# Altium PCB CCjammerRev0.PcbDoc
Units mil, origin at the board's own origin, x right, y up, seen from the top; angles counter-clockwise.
Board outline 3150 x 2000 mil, 2 copper layers (Top Layer, Bottom Layer); 11 components, 6 nets, 28 pads, 2 vias.
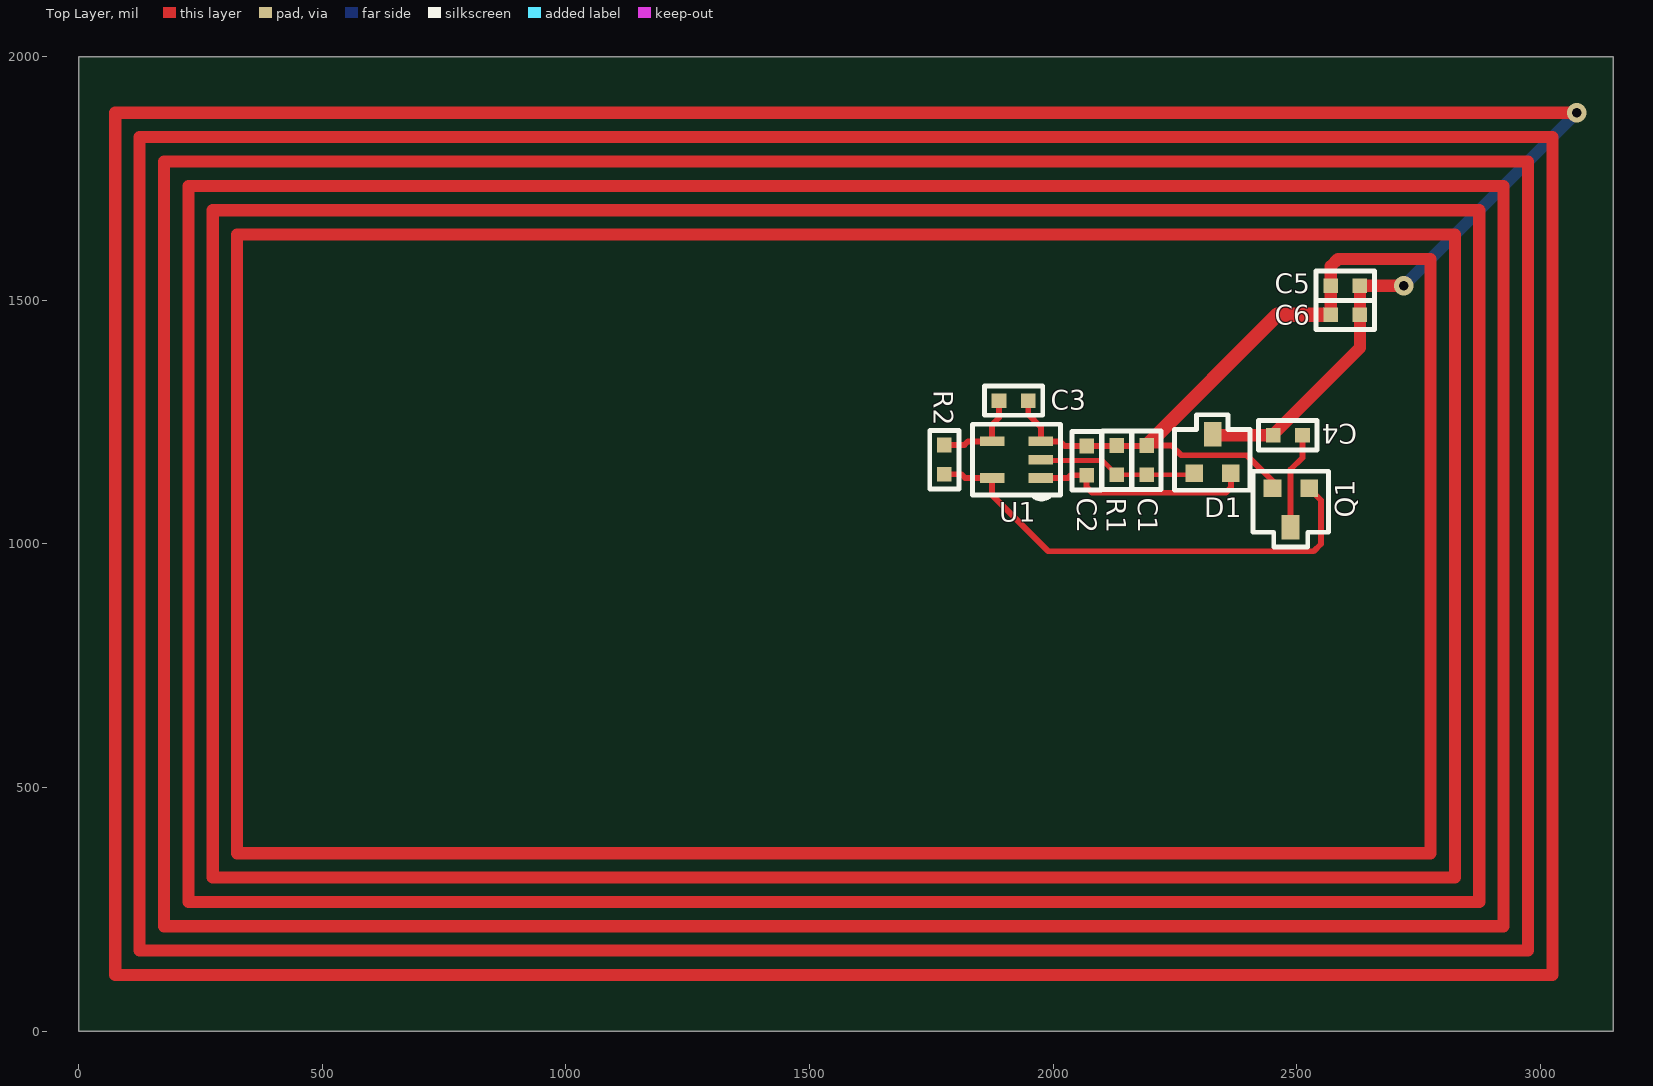
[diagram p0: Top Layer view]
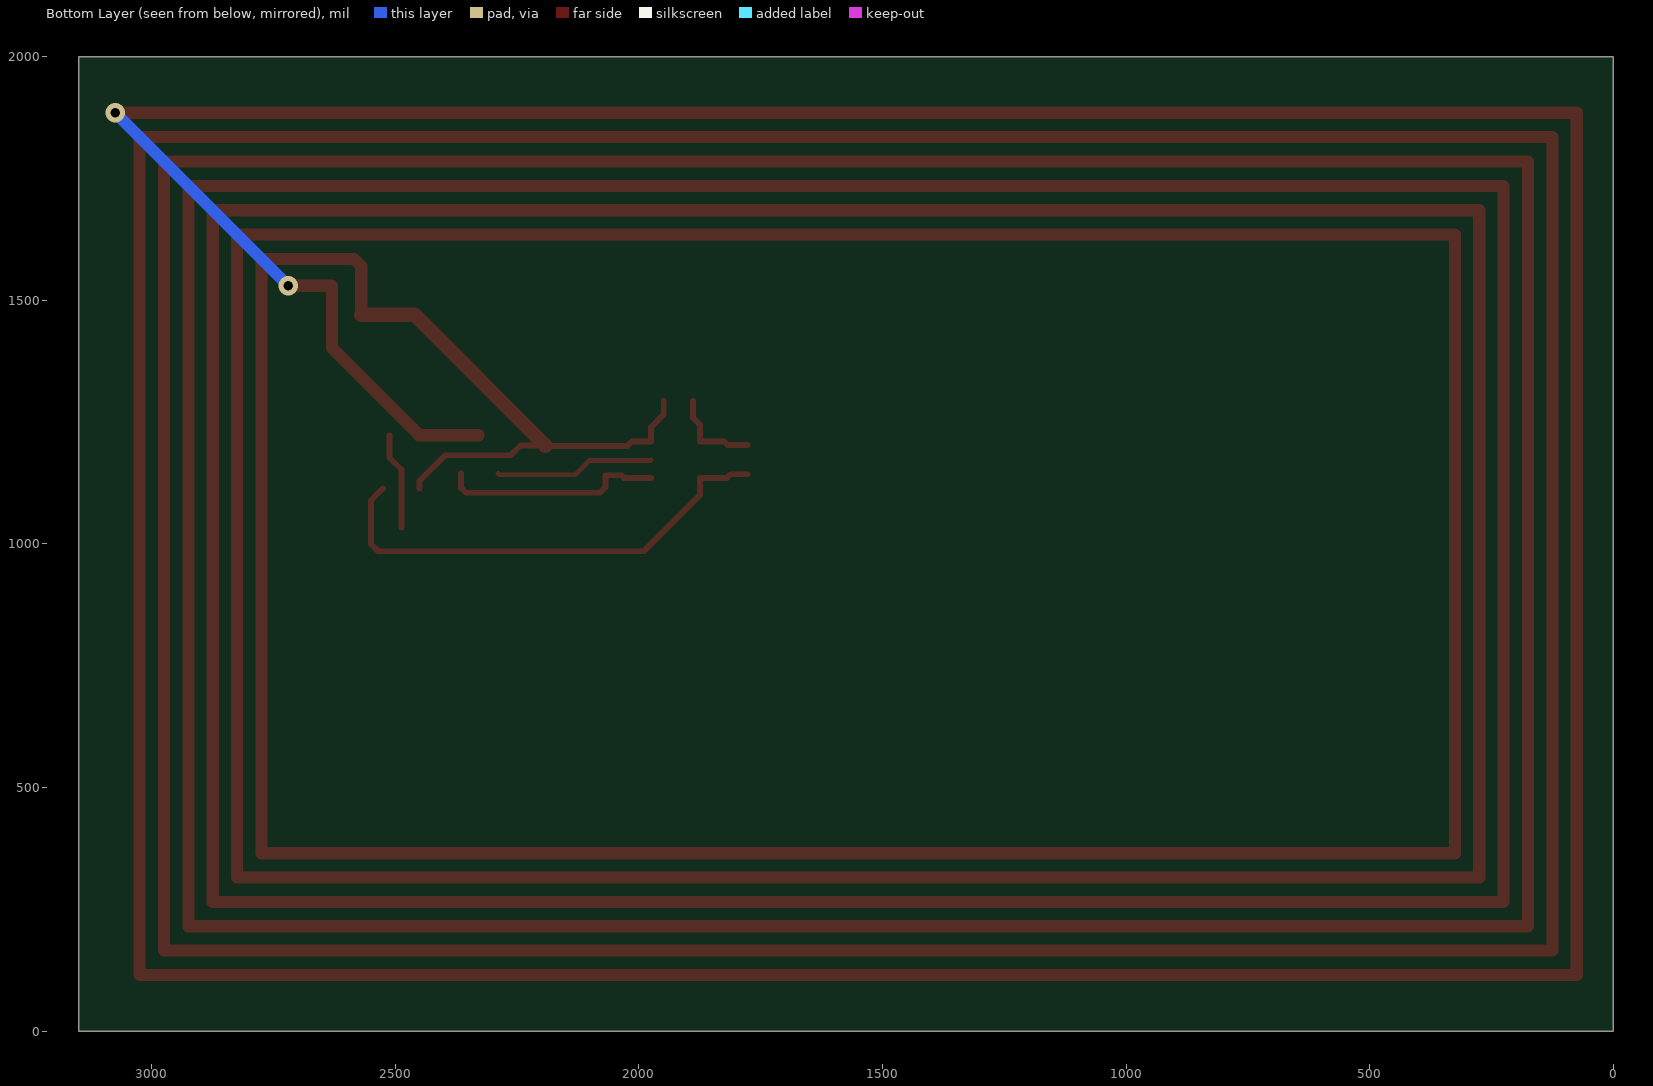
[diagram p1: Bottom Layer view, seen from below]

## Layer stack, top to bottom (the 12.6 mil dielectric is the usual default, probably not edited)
Top Layer: signal copper 1.4
Dielectric: dielectric 12.6, FR-4, Dk 4.8
Bottom Layer: signal copper 1.4

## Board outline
0,0 0,2000 3150,2000 3150,0

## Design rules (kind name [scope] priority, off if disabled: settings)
Clearance [All] p1: gap=10
PolygonConnect [All] p1: connectstyle=Relief reliefconductorwidth=10 reliefentries=4 polygonreliefangle="90 Angle"
RoutingVias [All] p1: holewidth=28 width=50 viastyle="Through Hole" minholewidth=28 minwidth=50 maxholewidth=28 maxwidth=50
SilkscreenOverComponentPads [All] p1: minsilkscreentomaskgap=10
SolderMaskExpansion [All] p1: expansion=4
Width [All] p1: maxlimit=100 minlimit=6 preferedwidth=10
27 further rules are at their usual default settings.

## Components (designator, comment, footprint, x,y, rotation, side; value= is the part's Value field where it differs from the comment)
C1 "270pf" 0603_072205 2192,1172 r270 top
C2 "0.1uf" 0603_072205 2069,1171 r270 top
C3 "10uf" 0603_072205 1919,1294 r180 top
C4 "10pf" 0603_072205 2482,1223 r180 top
C5 "10pf" 0603_072205 2600,1530 r0 top
C6 "10pf" 0603_072205 2600,1470 r0 top
D1 "BAT721A" SOT23_012105 2327,1185 r0 top
Q1 "VN0605" "SOT23 FET_012005" 2488,1074 r180 top
R1 "500K" 0603_072205 2131,1172 r270 top
R2 "46K" 0603_072205 1777,1173 r270 top
U1 "MIC1555" SOT25_030205 1925,1173 r0 top

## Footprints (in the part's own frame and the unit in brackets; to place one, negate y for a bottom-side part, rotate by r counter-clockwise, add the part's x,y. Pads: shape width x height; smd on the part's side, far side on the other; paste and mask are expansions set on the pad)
0603_072205 [mil] "SM"
  rect 30x30 smd: 1(-30,0) 2(30,0)
  silkscreen extent -60,-30 60,30
"SOT23 FET_012005" [mil] "SMT"
  rect 36x50 smd: D(0.5,40)
  rect 36x36 smd: G(-37.5,-40) S(37.5,-40)
  silkscreen extent -78,-75 78,80
SOT23_012105 [mil] "SMT"
  rect 36x36 smd: 1(-37.5,-40) 2(37.5,-40)
  rect 36x50 smd: 3(0.5,40)
  silkscreen extent -78,-75 78,80
SOT25_030205 [mil] "SMT"
  rect 50x20 smd: 1(50,-37.5) 2(50,-0.5) 3(50,37.5) 4(-50,37.5) 5(-50,-37.5)
  round 30 on Mech1 paste+0 mask+0: 1(65,-75)
  silkscreen extent -90,-81 90,72

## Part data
C1 C2 C3 C4 C5 C6: library part Cap, "Capacitor"
D1: library part DIODE_DUAL_COM_AN_SOT23
Q1: library part "FET N CHANNEL"
R1 R2: library part RESISTOR

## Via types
v1: diameter 40, hole 20, Top Layer to Bottom Layer, 2 vias

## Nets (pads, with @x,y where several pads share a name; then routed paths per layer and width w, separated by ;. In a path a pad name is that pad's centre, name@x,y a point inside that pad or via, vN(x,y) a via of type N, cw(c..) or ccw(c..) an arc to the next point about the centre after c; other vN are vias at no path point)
ANTENNA: C1.1 C2.1 C3.1 C4.2 C5.1 C5.2 C6.1 C6.2 D1.3 Q1.S R1.1 U1.3 | length 53154.7
  Top Layer w12: C3.1 1949,1266 1975,1240 U1.3 2014.5,1210.5 2024,1201 C2.1 C1.1@2192,1201 ; C1.1 2243,1202 2262.94,1182.06 2397.94,1182.06 2450.5,1129.5 Q1.S
  Top Layer w25: D1.3@2329.5,1223 C4.2 2452,1224.82 2630,1402.82 C6.2 C5.2 v1(2720,1530) ; C6.1 C5.1 2570,1570 2585,1585 2775,1585 2775,365 325,365 325,1635 2825,1635 2825,315 275,315 275,1685 2875,1685 2875,265 225,265 225,1735 2925,1735 2925,215 175,215 175,1785 2975,1785 2975,165 125,165 125,1835 3025,1835 3025,115 75,115 75,1885 v1(3075,1885)
  Top Layer w30: C1.1 2460,1470 C6.1
  Bottom Layer w25: v1(2720,1530) v1(3075,1885)
GATEDRV: Q1.G R2.2 U1.5 | length 989.6
  Top Layer w12: R2.2 1812,1143 1819.5,1135.5 U1.5 1875,1100 1990,985 2535,985 2550,1000 2550,1089.5 Q1.G
NetC4_1: C4.1 Q1.D | length 199.1
  Top Layer w12: Q1.D 2487.5,1152.5 2512,1177 C4.1
SIGNAL: C1.2 D1.1 R1.2 U1.2 | length 328.4
  Top Layer w10: U1.2 1976.5,1171 2102,1171 R1.2 C1.2 2286.5,1142 D1.1
THR: C3.2 R2.1 U1.4 | length 190.4
  Top Layer w12: R2.1 1818,1203 1825.5,1210.5 U1.4 1875,1245 1889,1259 C3.2
VCC: C2.2 D1.2 U1.1@1975,1135.5 | length 455.5
  Top Layer w12: U1.1@1975,1135.5 2030.5,1135.5 2036,1141 C2.2 2069,1116 2080,1105 2355,1105 2365,1115 D1.2@2365,1144.5
pads on no net: U1.1@1990,1098

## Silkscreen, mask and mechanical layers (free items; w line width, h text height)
Outline:
  the board outline again, w10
